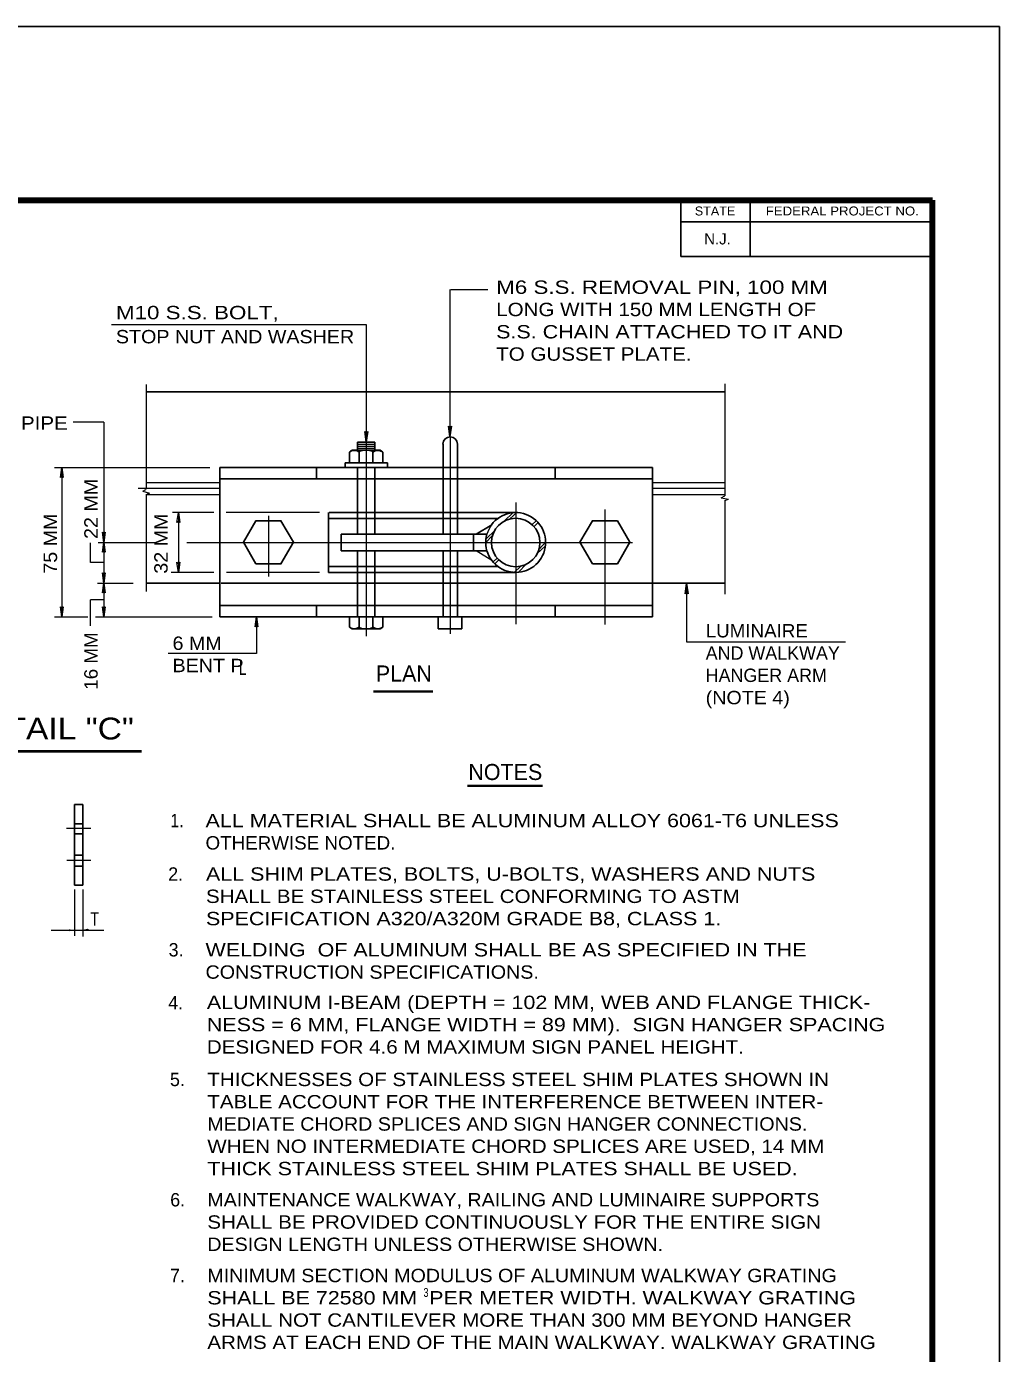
# Model space of a CAD drawing. Extents: x 312601.858 to 312602.699, y 144420.109 to 144420.704.
# Drawn here: x 312602.4805 to 312602.6988, y 144420.4057 to 144420.7035 of the extents above; entities that cross this region are included whole.
import ezdxf
from ezdxf.enums import TextEntityAlignment as Align

# ---------------------------------------------------------------- set-up
doc = ezdxf.new("R2010")
doc.units = 0
doc.header["$LTSCALE"] = 0.0012
for name, pattern in [('DOT_DASHED', [7.7, 5, -1.2, 0.3, -1.2]), ('LONG_DASHED', [7.5, 6, -1.5]), ('SHORT_DASHED', [2.7, 1.5, -1.2])]:
    doc.linetypes.add(name, pattern=pattern)
for name, color, linetype, lineweight in [('1', 7, 'Continuous', 13), ('2', 7, 'Continuous', 13), ('39', 7, 'Continuous', 13), ('61', 7, 'Continuous', 25)]:
    doc.layers.add(name, color=color, linetype=linetype, lineweight=lineweight)

msp = doc.modelspace()

# ---------------------------------------------------------------- hatches: boundary and pattern name
at = {"layer": '39'}
for points in [[(312602.5755, 144420.6136), (312602.5759, 144420.6138), (312602.5755, 144420.6114), (312602.5752, 144420.6138)], [(312602.5567, 144420.6124), (312602.5571, 144420.6126), (312602.5567, 144420.6102), (312602.5564, 144420.6126)], [(312602.6286, 144420.5764), (312602.6283, 144420.5762), (312602.6286, 144420.5786), (312602.629, 144420.5762)]]:
    msp.add_hatch(color=256, dxfattribs=at).paths.add_polyline_path(points)

# ---------------------------------------------------------------- linework, layer by layer
at = {"layer": '1'}
for p, q in [((312602.5755, 144420.6445), (312602.5755, 144420.6114)), ((312602.5757, 144420.6445), (312602.584, 144420.6445)), ((312602.4996, 144420.6366), (312602.5567, 144420.6366)), ((312602.5567, 144420.6366), (312602.5567, 144420.6102)), ((312602.5074, 144420.6232), (312602.5074, 144420.5997)), ((312602.6372, 144420.6233), (312602.6372, 144420.5982)), ((312602.5548, 144420.6098), (312602.5587, 144420.6098)), ((312602.5548, 144420.6093), (312602.5587, 144420.6093)), ((312602.5548, 144420.6089), (312602.5587, 144420.6089)), ((312602.4868, 144420.6045), (312602.5217, 144420.6045)), ((312602.4885, 144420.6045), (312602.4885, 144420.571)), ((312602.5066, 144420.5992), (312602.5073, 144420.5996)), ((312602.5066, 144420.5992), (312602.5081, 144420.5988)), ((312602.5074, 144420.5985), (312602.5081, 144420.5988)), ((312602.5074, 144420.5985), (312602.5074, 144420.5767)), ((312602.6364, 144420.5977), (312602.6372, 144420.5982)), ((312602.6364, 144420.5977), (312602.638, 144420.5974)), ((312602.6372, 144420.5971), (312602.638, 144420.5974)), ((312602.6372, 144420.5971), (312602.6372, 144420.5761)), ((312602.5226, 144420.5944), (312602.5133, 144420.5944)), ((312602.5146, 144420.5944), (312602.5146, 144420.581)), ((312602.5463, 144420.5944), (312602.5253, 144420.5944)), ((312602.5877, 144420.5925), (312602.5897, 144420.5944)), ((312602.589, 144420.593), (312602.5905, 144420.5944)), ((312602.5939, 144420.5917), (312602.5949, 144420.5926)), ((312602.5837, 144420.5886), (312602.5855, 144420.5903)), ((312602.5848, 144420.5916), (312602.5849, 144420.5917)), ((312602.5944, 144420.5913), (312602.5953, 144420.5922)), ((312602.4966, 144420.5877), (312602.5095, 144420.5877)), ((312602.5836, 144420.5877), (312602.585, 144420.5892)), ((312602.5951, 144420.5852), (312602.5969, 144420.5869)), ((312602.5956, 144420.5863), (312602.597, 144420.5878)), ((312602.5848, 144420.5838), (312602.5849, 144420.5837)), ((312602.5852, 144420.5834), (312602.5861, 144420.5842)), ((312602.5856, 144420.5829), (312602.5865, 144420.5838)), ((312602.5226, 144420.581), (312602.513, 144420.581)), ((312602.5463, 144420.581), (312602.5254, 144420.581)), ((312602.5899, 144420.581), (312602.5914, 144420.5824)), ((312602.5908, 144420.581), (312602.5927, 144420.5829)), ((312602.4965, 144420.5786), (312602.5045, 144420.5786)), ((312602.4868, 144420.571), (312602.4943, 144420.571)), ((312602.496, 144420.571), (312602.5222, 144420.571)), ((312602.4913, 144420.5098), (312602.4913, 144420.4994)), ((312602.4932, 144420.5098), (312602.4932, 144420.4993))]:
    msp.add_line(p, q, dxfattribs=at)
at = {"layer": '1', "lineweight": 25}
for p, q in [((312602.5074, 144420.6215), (312602.6372, 144420.6215)), ((312602.553, 144420.608), (312602.5536, 144420.6084)), ((312602.553, 144420.608), (312602.553, 144420.6056)), ((312602.5536, 144420.6084), (312602.5599, 144420.6084)), ((312602.5548, 144420.6102), (312602.5587, 144420.6102)), ((312602.5548, 144420.6102), (312602.5548, 144420.6084)), ((312602.5552, 144420.608), (312602.5552, 144420.6056)), ((312602.5582, 144420.608), (312602.5582, 144420.6056)), ((312602.5587, 144420.6102), (312602.5587, 144420.6084)), ((312602.5605, 144420.608), (312602.5599, 144420.6084)), ((312602.5605, 144420.608), (312602.5605, 144420.6056)), ((312602.574, 144420.6098), (312602.574, 144420.6045)), ((312602.5772, 144420.6098), (312602.5772, 144420.6045)), ((312602.5239, 144420.6045), (312602.621, 144420.6045)), ((312602.5239, 144420.6045), (312602.5239, 144420.571)), ((312602.5456, 144420.6045), (312602.5456, 144420.602)), ((312602.552, 144420.6056), (312602.552, 144420.6045)), ((312602.552, 144420.6056), (312602.5615, 144420.6056)), ((312602.5615, 144420.6056), (312602.5615, 144420.6045)), ((312602.5991, 144420.6045), (312602.5991, 144420.602)), ((312602.621, 144420.6045), (312602.621, 144420.571)), ((312602.5239, 144420.602), (312602.621, 144420.602)), ((312602.5548, 144420.602), (312602.5548, 144420.5944)), ((312602.5587, 144420.602), (312602.5587, 144420.5944)), ((312602.574, 144420.602), (312602.574, 144420.5944)), ((312602.5772, 144420.602), (312602.5772, 144420.5944)), ((312602.5483, 144420.5944), (312602.5483, 144420.581)), ((312602.5903, 144420.5944), (312602.5484, 144420.5944)), ((312602.5511, 144420.5896), (312602.5511, 144420.5858)), ((312602.5511, 144420.5896), (312602.5814, 144420.5896)), ((312602.5808, 144420.5896), (312602.5808, 144420.5858)), ((312602.5511, 144420.5858), (312602.5838, 144420.5858)), ((312602.5903, 144420.581), (312602.5483, 144420.581)), ((312602.5548, 144420.581), (312602.5548, 144420.5736)), ((312602.5587, 144420.581), (312602.5587, 144420.5736)), ((312602.574, 144420.581), (312602.574, 144420.5736)), ((312602.5772, 144420.581), (312602.5772, 144420.5736)), ((312602.5074, 144420.5786), (312602.5239, 144420.5786)), ((312602.621, 144420.5786), (312602.6372, 144420.5786)), ((312602.5239, 144420.5736), (312602.621, 144420.5736)), ((312602.5456, 144420.5736), (312602.5456, 144420.571)), ((312602.5991, 144420.5736), (312602.5991, 144420.571)), ((312602.5239, 144420.571), (312602.621, 144420.571)), ((312602.553, 144420.5687), (312602.553, 144420.571)), ((312602.5552, 144420.5687), (312602.5552, 144420.571)), ((312602.5582, 144420.5687), (312602.5582, 144420.571)), ((312602.5605, 144420.5687), (312602.5605, 144420.571)), ((312602.5729, 144420.5683), (312602.5729, 144420.571)), ((312602.5782, 144420.5683), (312602.5782, 144420.571)), ((312602.553, 144420.5687), (312602.5536, 144420.5683)), ((312602.5536, 144420.5683), (312602.5599, 144420.5683)), ((312602.5605, 144420.5687), (312602.5599, 144420.5683)), ((312602.5729, 144420.5683), (312602.5782, 144420.5683)), ((312602.4913, 144420.5289), (312602.4913, 144420.5108)), ((312602.4913, 144420.5289), (312602.4932, 144420.5289)), ((312602.4932, 144420.5289), (312602.4932, 144420.5108)), ((312602.4913, 144420.5246), (312602.4932, 144420.5246)), ((312602.4913, 144420.5223), (312602.4932, 144420.5223)), ((312602.4913, 144420.5175), (312602.4932, 144420.5175)), ((312602.4913, 144420.5151), (312602.4932, 144420.5151)), ((312602.4932, 144420.5108), (312602.4913, 144420.5108))]:
    msp.add_line(p, q, dxfattribs=at)
at = {"layer": '1', "linetype": 'DOT_DASHED'}
for p, q in [((312602.5756, 144420.6113), (312602.5756, 144420.5672)), ((312602.5567, 144420.6104), (312602.5567, 144420.5667)), ((312602.5056, 144420.5999), (312602.5239, 144420.5999)), ((312602.621, 144420.5999), (312602.6372, 144420.5999)), ((312602.5903, 144420.5967), (312602.5903, 144420.5694)), ((312602.5348, 144420.5937), (312602.5348, 144420.5801)), ((312602.6103, 144420.5951), (312602.6103, 144420.5693)), ((312602.6103, 144420.5937), (312602.6103, 144420.5801)), ((312602.5165, 144420.5877), (312602.6184, 144420.5877)), ((312602.495, 144420.5235), (312602.4895, 144420.5235)), ((312602.495, 144420.5163), (312602.4896, 144420.5163))]:
    msp.add_line(p, q, dxfattribs=at)
at = {"layer": '1', "linetype": 'SHORT_DASHED', "lineweight": 25}
for p, q in [((312602.5548, 144420.6045), (312602.5548, 144420.602)), ((312602.5587, 144420.6045), (312602.5587, 144420.602)), ((312602.574, 144420.6045), (312602.574, 144420.602)), ((312602.5772, 144420.6045), (312602.5772, 144420.602)), ((312602.5548, 144420.5944), (312602.5548, 144420.5896)), ((312602.5587, 144420.5944), (312602.5587, 144420.5896)), ((312602.574, 144420.5944), (312602.574, 144420.5896)), ((312602.5772, 144420.5944), (312602.5772, 144420.5896)), ((312602.5548, 144420.5858), (312602.5548, 144420.581)), ((312602.5587, 144420.5858), (312602.5587, 144420.581)), ((312602.574, 144420.5858), (312602.574, 144420.581)), ((312602.5772, 144420.5858), (312602.5772, 144420.581)), ((312602.5548, 144420.5736), (312602.5548, 144420.571)), ((312602.5587, 144420.5736), (312602.5587, 144420.571)), ((312602.574, 144420.5736), (312602.574, 144420.571)), ((312602.5772, 144420.5736), (312602.5772, 144420.571))]:
    msp.add_line(p, q, dxfattribs=at)
at = {"layer": '1', "linetype": 'LONG_DASHED'}
for p, q in [((312602.5074, 144420.6012), (312602.5239, 144420.6012)), ((312602.621, 144420.6012), (312602.6372, 144420.6012)), ((312602.5074, 144420.5985), (312602.5239, 144420.5985)), ((312602.621, 144420.5985), (312602.6372, 144420.5985))]:
    msp.add_line(p, q, dxfattribs=at)
at = {"layer": '1', "linetype": 'LONG_DASHED', "lineweight": 25}
for p, q in [((312602.5483, 144420.5931), (312602.5864, 144420.5931)), ((312602.5483, 144420.5823), (312602.5864, 144420.5823)), ((312602.5242, 144420.5786), (312602.621, 144420.5786))]:
    msp.add_line(p, q, dxfattribs=at)
at = {"layer": '1'}
for points in [[(312602.4979, 144420.6147), (312602.4979, 144420.5877), (312602.4979, 144420.5786), (312602.4979, 144420.571)], [(312602.5849, 144420.5917), (312602.5814, 144420.5896), (312602.5838, 144420.5896)], [(312602.5838, 144420.5896), (312602.5814, 144420.5896), (312602.5849, 144420.5917), (312602.5848, 144420.5916)], [(312602.5849, 144420.5837), (312602.5814, 144420.5858), (312602.5838, 144420.5858)], [(312602.6286, 144420.5786), (312602.6286, 144420.5654), (312602.6643, 144420.5654)], [(312602.5321, 144420.571), (312602.5321, 144420.5628), (312602.5123, 144420.5628)], [(312602.4861, 144420.5007), (312602.4913, 144420.5007), (312602.4932, 144420.5007), (312602.4979, 144420.5007)]]:
    msp.add_lwpolyline(points, dxfattribs=at)
for points in [[(312602.4882, 144420.6023), (312602.4885, 144420.6045), (312602.4888, 144420.6023), (312602.4885, 144420.6025)], [(312602.5143, 144420.5922), (312602.5146, 144420.5944), (312602.5149, 144420.5922), (312602.5146, 144420.5924)], [(312602.4982, 144420.59), (312602.4979, 144420.5877), (312602.4976, 144420.59), (312602.4979, 144420.5897)], [(312602.4976, 144420.5855), (312602.4979, 144420.5877), (312602.4982, 144420.5855), (312602.4979, 144420.5857)], [(312602.4982, 144420.5809), (312602.4979, 144420.5786), (312602.4976, 144420.5809), (312602.4979, 144420.5806)], [(312602.5149, 144420.5833), (312602.5146, 144420.581), (312602.5143, 144420.5833), (312602.5146, 144420.583)], [(312602.4976, 144420.5764), (312602.4979, 144420.5786), (312602.4982, 144420.5764), (312602.4979, 144420.5766)], [(312602.4888, 144420.5733), (312602.4885, 144420.571), (312602.4882, 144420.5733), (312602.4885, 144420.573)], [(312602.4982, 144420.5733), (312602.4979, 144420.571), (312602.4976, 144420.5733), (312602.4979, 144420.573)], [(312602.5318, 144420.5688), (312602.5321, 144420.571), (312602.5324, 144420.5688), (312602.5321, 144420.569)]]:
    msp.add_lwpolyline(points, close=True, dxfattribs=at)
at = {"layer": '1', "lineweight": 25}
for points in [[(312602.532, 144420.5829), (312602.5376, 144420.5829), (312602.5404, 144420.5878), (312602.5376, 144420.5926), (312602.532, 144420.5926), (312602.5292, 144420.5878)], [(312602.6075, 144420.5829), (312602.6131, 144420.5829), (312602.6159, 144420.5878), (312602.6131, 144420.5926), (312602.6075, 144420.5926), (312602.6047, 144420.5878)]]:
    msp.add_lwpolyline(points, close=True, dxfattribs=at)
msp.add_circle((312602.590285, 144420.587705), 0.00544, dxfattribs=at)
for centre, radius, start, end in [((312602.554075, 144420.60649), 0.001872, 53.82173, 116.36509), ((312602.559345, 144420.60649), 0.001872, 56.30993, 126.17827), ((312602.590285, 144420.587705), 0.006715, 163.83043, 143.98606), ((312602.554075, 144420.570195), 0.001872, 243.63491, 306.17827), ((312602.559345, 144420.570195), 0.001872, 233.82173, 296.36509)]:
    msp.add_arc(centre, radius, start, end, dxfattribs=at)
at = {"layer": '1'}
for centre, radius, start, end in [((312602.55671, 144420.604747), 0.003612, 64.94239, 115.05762), ((312602.590285, 144420.587705), 0.006715, 143.98606, 163.83043), ((312602.590285, 144420.587705), 0.006715, 143.98606, 163.83043), ((312602.590285, 144420.587705), 0.006715, 196.16957, 216.01394), ((312602.55671, 144420.571938), 0.003612, 244.94238, 295.05761)]:
    msp.add_arc(centre, radius, start, end, dxfattribs=at)
at = {"layer": '1', "lineweight": 25}
msp.add_ellipse((312602.57558, 144420.609805), major_axis=(0.001623, 0.000171), ratio=0.995348, start_param=6.1788327, end_param=9.319901, dxfattribs=at)
at = {"layer": '2'}
for p, q in [((312602.4979, 144420.6147), (312602.491, 144420.6147)), ((312602.4979, 144420.5748), (312602.4949, 144420.5748)), ((312602.4949, 144420.569), (312602.4949, 144420.5748))]:
    msp.add_line(p, q, dxfattribs=at)
at = {"layer": '2', "lineweight": 35}
for p, q in [((312602.5584, 144420.5543), (312602.5717, 144420.5543)), ((312602.5795, 144420.5331), (312602.5963, 144420.5331))]:
    msp.add_line(p, q, dxfattribs=at)
at = {"layer": '2', "lineweight": 40}
msp.add_line((312602.3981, 144420.5409), (312602.5063, 144420.5409), dxfattribs=at)
at = {"layer": '2'}
msp.add_lwpolyline([(312602.4979, 144420.5832), (312602.4949, 144420.5832), (312602.4949, 144420.5876)], dxfattribs=at)
for points in [[(312602.4902, 144420.5008), (312602.4913, 144420.5007), (312602.4902, 144420.5006), (312602.4903, 144420.5007)], [(312602.4943, 144420.5006), (312602.4932, 144420.5007), (312602.4943, 144420.5009), (312602.4942, 144420.5007)]]:
    msp.add_lwpolyline(points, close=True, dxfattribs=at)
at = {"layer": '39', "lineweight": 25}
for p, q in [((312601.8578, 144420.7035), (312602.6988, 144420.7035)), ((312602.6838, 144420.6514), (312602.6838, 144420.6645))]:
    msp.add_line(p, q, dxfattribs=at)
msp.add_lwpolyline([(312601.8578, 144420.1095), (312602.6988, 144420.1095), (312602.6988, 144420.7035)], dxfattribs=at)
at = {"layer": '39', "lineweight": 158}
for points in [[(312601.9088, 144420.1245), (312602.6838, 144420.1245), (312602.6838, 144420.6645)], [(312601.9088, 144420.1247), (312601.9088, 144420.6645), (312602.6838, 144420.6645)]]:
    msp.add_lwpolyline(points, dxfattribs=at)
at = {"layer": '39'}
for points in [[(312602.5755, 144420.6136), (312602.5759, 144420.6138), (312602.5755, 144420.6114), (312602.5752, 144420.6138)], [(312602.5567, 144420.6124), (312602.5571, 144420.6126), (312602.5567, 144420.6102), (312602.5564, 144420.6126)], [(312602.6286, 144420.5764), (312602.6283, 144420.5762), (312602.6286, 144420.5786), (312602.629, 144420.5762)]]:
    msp.add_lwpolyline(points, close=True, dxfattribs=at)
at = {"layer": '61'}
for p, q in [((312602.6273, 144420.6645), (312602.6273, 144420.6519)), ((312602.6429, 144420.6645), (312602.6429, 144420.6519)), ((312602.6838, 144420.6597), (312602.6273, 144420.6597)), ((312602.6838, 144420.6519), (312602.6273, 144420.6519))]:
    msp.add_line(p, q, dxfattribs=at)

# ---------------------------------------------------------------- texts
at = {"layer": '2'}
for s, height, width, p in [('M6 S.S. REMOVAL PIN, 100 MM', 0.003, 1.25, (312602.5859, 144420.6435)), ('M10 S.S. BOLT,', 0.003, 1.25, (312602.5006, 144420.6378)), ('LONG WITH 150 MM LENGTH OF', 0.003, 1.15, (312602.5859, 144420.6385)), ('STOP NUT AND WASHER', 0.003, 1.1, (312602.5006, 144420.6324)), ('S.S. CHAIN ATTACHED TO IT AND', 0.003, 1.2, (312602.5859, 144420.6335)), ('TO GUSSET PLATE.', 0.003, 1.15, (312602.5859, 144420.6285)), ('OF PIPE', 0.003, 1.15, (312602.4716, 144420.613)), ('LUMINAIRE', 0.003, 1.05, (312602.6329, 144420.5664)), ('6 MM', 0.003, 1.1, (312602.5133, 144420.5636)), ('BENT P', 0.003, 1.1, (312602.5133, 144420.5586)), ('(NOTE 4)', 0.003, 1.1, (312602.6329, 144420.5514)), ('HANDRAIL HINGE DETAIL "C"', 0.0049, 1.15, (312602.3992, 144420.5435)), ('ALL MATERIAL SHALL BE ALUMINUM ALLOY 6061-T6 UNLESS', 0.003, 1.2, (312602.5207, 144420.5238)), ('OTHERWISE NOTED.', 0.003, 1.05, (312602.5207, 144420.5188)), ('ALL SHIM PLATES, BOLTS, U-BOLTS, WASHERS AND NUTS', 0.003, 1.2, (312602.5208, 144420.5118)), ('SHALL BE STAINLESS STEEL CONFORMING TO ASTM ', 0.003, 1.15, (312602.5208, 144420.5068)), ('SPECIFICATION A320/A320M GRADE B8, CLASS 1.', 0.003, 1.2, (312602.5208, 144420.5018)), ('WELDING  OF ALUMINUM SHALL BE AS SPECIFIED IN THE', 0.003, 1.2, (312602.5207, 144420.4948)), ('CONSTRUCTION SPECIFICATIONS.', 0.003, 1.1, (312602.5207, 144420.4898)), ('ALUMINUM I-BEAM (DEPTH = 102 MM, WEB AND FLANGE THICK-', 0.003, 1.2, (312602.521, 144420.483)), ('NESS = 6 MM, FLANGE WIDTH = 89 MM).  SIGN HANGER SPACING', 0.003, 1.2, (312602.521, 144420.478)), ('DESIGNED FOR 4.6 M MAXIMUM SIGN PANEL HEIGHT.', 0.003, 1.15, (312602.521, 144420.473)), ('THICKNESSES OF STAINLESS STEEL SHIM PLATES SHOWN IN ', 0.003, 1.15, (312602.5211, 144420.4657)), ('TABLE ACCOUNT FOR THE INTERFERENCE BETWEEN INTER-', 0.003, 1.15, (312602.5211, 144420.4607)), ('MEDIATE CHORD SPLICES AND SIGN HANGER CONNECTIONS.', 0.003, 1.1, (312602.5211, 144420.4557)), ('WHEN NO INTERMEDIATE CHORD SPLICES ARE USED, 14 MM', 0.003, 1.15, (312602.5211, 144420.4507)), ('THICK STAINLESS STEEL SHIM PLATES SHALL BE USED. ', 0.003, 1.2, (312602.5211, 144420.4457)), ('MAINTENANCE WALKWAY, RAILING AND LUMINAIRE SUPPORTS', 0.003, 1.1, (312602.5211, 144420.4387)), ('SHALL BE PROVIDED CONTINUOUSLY FOR THE ENTIRE SIGN', 0.003, 1.15, (312602.5211, 144420.4337)), ('DESIGN LENGTH UNLESS OTHERWISE SHOWN.', 0.003, 1.1, (312602.5211, 144420.4287)), ('MINIMUM SECTION MODULUS OF ALUMINUM WALKWAY GRATING', 0.003, 1.1, (312602.5211, 144420.4217)), ('SHALL BE 72580 MM  PER METER WIDTH. WALKWAY GRATING ', 0.003, 1.2, (312602.5211, 144420.4167)), ('SHALL NOT CANTILEVER MORE THAN 300 MM BEYOND HANGER', 0.003, 1.15, (312602.5211, 144420.4117)), ('ARMS AT EACH END OF THE MAIN WALKWAY. WALKWAY GRATING ', 0.003, 1.15, (312602.5211, 144420.4067))]:
    msp.add_text(s, height=height, dxfattribs=dict(at, width=width)).set_placement(p)
for s, width, p in [('22 MM', 1.1, (312602.4965, 144420.59525)), ('75 MM', 1.1, (312602.4874, 144420.58745)), ('32 MM', 1.1, (312602.5122, 144420.58745)), ('16 MM', 1.05, (312602.4965, 144420.5611))]:
    msp.add_text(s, height=0.003, rotation=90, dxfattribs=dict(at, width=width)).set_placement(p, align=Align.CENTER)
for s, height, p in [('AND WALKWAY', 0.003, (312602.6329, 144420.5614)), ('PLAN', 0.0036, (312602.5589, 144420.5565)), ('HANGER ARM', 0.003, (312602.6329, 144420.5564))]:
    msp.add_text(s, height=height, dxfattribs=at).set_placement(p)
for s, height, width, p in [('L', 0.003, 0.75, (312602.52905, 144420.558)), ('1.', 0.003, 0.9, (312602.5143, 144420.5238)), ('T', 0.003, 0.8, (312602.49585, 144420.5017)), ('3', 0.002, 0.75, (312602.57015, 144420.4184))]:
    msp.add_text(s, height=height, dxfattribs=dict(at, width=width)).set_placement(p, align=Align.CENTER)
for s, height, p in [('NOTES', 0.0036, (312602.58795, 144420.5344)), ('2.', 0.003, (312602.514, 144420.5118)), ('3.', 0.003, (312602.5141, 144420.4948)), ('4.', 0.003, (312602.514, 144420.4829)), ('5.', 0.003, (312602.5144, 144420.4657)), ('6.', 0.003, (312602.51445, 144420.4387)), ('7.', 0.003, (312602.5144, 144420.4217))]:
    msp.add_text(s, height=height, dxfattribs=at).set_placement(p, align=Align.CENTER)
at = {"layer": '61'}
for s, width, p in [('STATE', 1.05, (312602.635, 144420.6611)), ('FEDERAL PROJECT NO.', 1.1, (312602.66355, 144420.6611))]:
    msp.add_text(s, height=0.00201, dxfattribs=dict(at, width=width)).set_placement(p, align=Align.CENTER)
msp.add_text('N.J.', height=0.002512, dxfattribs=at).set_placement((312602.63555, 144420.6546), align=Align.CENTER)

doc.saveas('drawing.dxf')
